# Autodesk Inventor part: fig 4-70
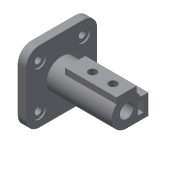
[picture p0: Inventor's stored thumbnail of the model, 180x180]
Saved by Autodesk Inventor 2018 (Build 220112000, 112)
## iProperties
Shininess: 77.0
Length Units: 11269
Angle Units: 11279
Time Units: 11290
Mass Units: 11283
Length Display Precision: 3
Angle Display Precision: 2
Created: 2001-12
Part Number: fig 4-70
Document SubType Name: Modeling
Designer: Renu Muthoo
Density: 1 g/cm^3
Material: Generic
Appearance: Default
Density: 0.0
Volumn: 0.0
Area: 0.0
PropertySet Name: Model Information
Control State: 0
Master: False
Checked Out: False
Author: Renu Muthoo
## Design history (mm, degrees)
node "Sketch1"
sketch "Sketch2"
  geometry: L1 (24.44, 30.488)-(-40.56, 30.488); L2 (-60.56, 10.488)-(-60.56, -54.512); L3 (-40.56, -74.512)-(24.44, -74.512); L4 (44.44, -54.512)-(44.44, 10.488); A1 r 20 centre (24.44, 10.488) between (44.44, 10.488) and (24.44, 30.488); A2 r 20 centre (-40.56, 10.488) between (-40.56, 30.488) and (-60.56, 10.488); A3 r 20 centre (-40.56, -54.512) between (-60.56, -54.512) and (-40.56, -74.512); A4 r 20 centre (24.44, -54.512) between (24.44, -74.512) and (44.44, -54.512); 2 further points
  constraints: 8 end point, 8 point on circle, 8 tangent, 4 centre point, 4 point on line, 3 equal radius, 2 parallel, 2 perpendicular, 1 horizontal
  dimensions: "d1" = 20 radius of A1; "d2" = 105 distance between parallel lines of L2 L4
extrude "Extrusion1" new body sketch "Sketch2" distance "d3" = 12; taper "d4" = 0 deg
sketch "Sketch3"
  geometry: A1 r 20 centre (-24.44, 10.488) between (-24.44, 30.488) and (-44.44, 10.488) reference; A2 r 20 centre (-24.44, -54.512) between (-44.44, -54.512) and (-24.44, -74.512) reference; A3 r 20 centre (40.56, -54.512) between (40.56, -74.512) and (60.56, -54.512) reference; A4 r 20 centre (40.56, 10.488) between (60.56, 10.488) and (40.56, 30.488) reference
hole "Hole1" sketch "Sketch3" at (-24.44, 10.488), (-24.44, -54.512), (40.56, 10.488), (40.56, -54.512) diameter "d5" = 10; stored, may be unused: countersink angle "d9" = 82 deg, drill point angle "d11" = 118 deg; dims "d6" = 6, "d7" = 20, "d8" = 2, "d10" = 8
sketch "Sketch4"
  geometry: L1 (-24.44, 30.488)-(40.56, 30.488) reference; L2 (-44.44, -54.512)-(-44.44, 10.488) reference; C1 r 22 at (8.06, -22.012)
  constraints: 1 centre point
  dimensions: "d12" = 52.5 distance from line of L2 C1.centre; "d13" = 52.5 distance from line of L1 C1.centre; "d14" = 44 diameter of C1
extrude "Extrusion2" join sketch "Sketch4" distance "d15" = 96; taper "d16" = 0 deg
sketch "Sketch5"
  geometry: L1 (-15, 16.093)-(15, 16.093); L2 (15, 16.093)-(15, 25); L3 (15, 25)-(-15, 25); L4 (-15, 25)-(-15, 16.093); 1 further point
  constraints: 8 end point, 2 parallel, 1 horizontal, 1 perpendicular, 2 other
  dimensions: "d17" = 30 distance of L2.end L3.end; "d18" = 25 distance from line of point (0, 0) L3; "d19" = 15 distance from line of point (0, 0) L4
extrude "Extrusion3" join sketch "Sketch5" distance "d20" = 76; taper "d21" = 0 deg
sketch "Sketch6"
  geometry: L1 (8, -44.012)-(40.06, -44.012); L2 (40.06, -44.012)-(40.06, -14.012); L3 (40.06, -14.012)-(8, -14.012); L4 (8, -14.012)-(8, -44.012); A1 r 22 centre (8.06, -22.012) between (-6.94, -5.918) and (23.06, -5.918) reference
  constraints: 8 end point, 2 parallel, 1 horizontal, 1 perpendicular, 1 tangent
  dimensions: "d22" = 32 distance from line of A1.centre L2; "d23" = 30 distance of L1.end L2.end
extrude "Extrusion4" join sketch "Sketch6" distance "d24" = 57; taper "d25" = 0 deg
sketch "Sketch7"
  geometry: L1 (25.06, -20.012)-(33.06, -20.012); L2 (33.06, -20.012)-(33.06, -36.012); L3 (33.06, -36.012)-(25.06, -36.012); L4 (25.06, -36.012)-(25.06, -20.012); A1 r 22 centre (8.06, -22.012) between (-6.94, -5.918) and (8, -44.012) reference
  constraints: 8 end point, 2 parallel, 1 horizontal, 1 perpendicular
  dimensions: "d26" = 8 distance of L2.end L3.end; "d27" = 16 distance of L1.end L2.end; "d28" = 25 distance from line of A1.centre L2; "d29" = 2 vertical distance of A1.centre L1.start
extrude "Extrusion5" cut sketch "Sketch7" distance "d30" = 35; taper "d31" = 0 deg
sketch "Sketch8"
  geometry: A1 r 22 centre (8.06, -22.012) between (-6.94, -5.918) and (8, -44.012) reference
hole "Hole2" sketch "Sketch8" at (8.06, -22.012) diameter "d32" = 20; stored, may be unused: countersink angle "d36" = 82 deg, drill point angle "d38" = 0 deg; dims "d33" = 6, "d34" = 20, "d35" = 2, "d37" = 96
sketch "Sketch9"
  geometry: L1 (0, 0)-(0, 76) reference; L2 (30, 0)-(0, 0) reference; 2 further points
  dimensions: "d39" = 20 distance from line of L2 point (15, 20); "d40" = 15 distance from line of L1 point (15, 20); "d41" = 30 distance of point (15, 50) point (15, 20)
hole "Hole3" sketch "Sketch9" at (15, 20), (15, 50) diameter "d42" = 12; stored, may be unused: countersink angle "d46" = 82 deg, drill point angle "d48" = 0 deg; dims "d43" = 6, "d44" = 20, "d45" = 2, "d47" = 25
sketch "Sketch10"
  geometry: L1 (30, 0)-(0, 0) reference; L2 (30, 0)-(30, 57) reference; 2 further points
  dimensions: "d49" = 15 distance from line of L1 point (15, 15); "d50" = 15 distance from line of L2 point (15, 15); "d51" = 22 distance of point (15, 37) point (15, 15)
hole "Hole4" sketch "Sketch10" at (15, 15), (15, 37) diameter "d52" = 10; stored, may be unused: countersink angle "d56" = 82 deg, drill point angle "d58" = 0 deg; dims "d53" = 6, "d54" = 20, "d55" = 2, "d57" = 7
body "Solid1"
